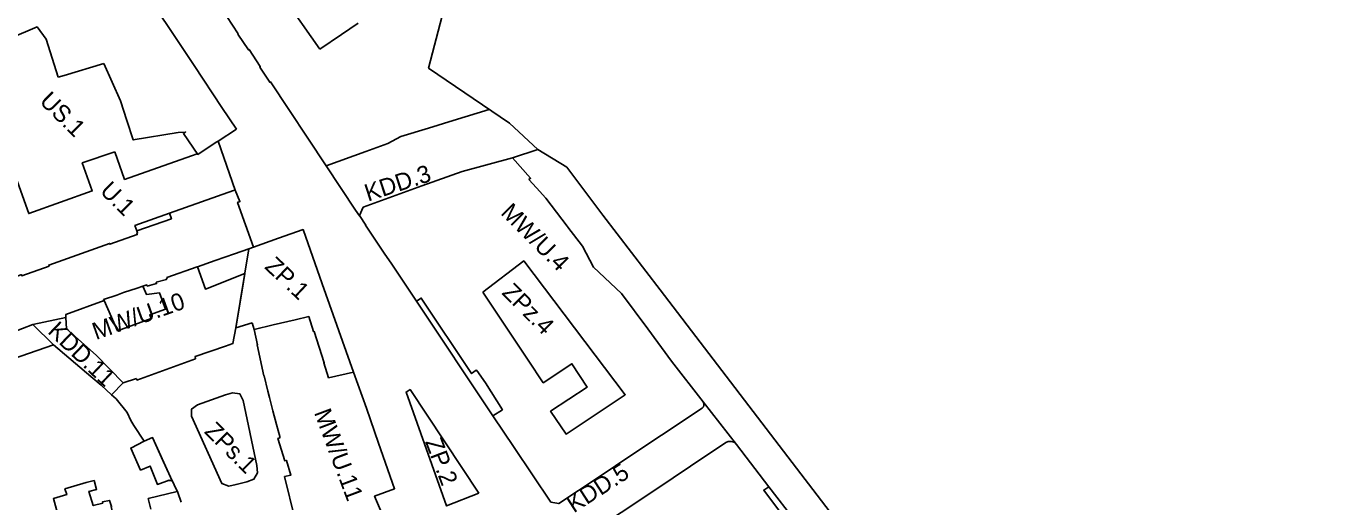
# Model space of a CAD drawing. Extents: x 7423835 to 7425280, y 5546086 to 5547600.
# Drawn here: x 7424593.5 to 7425051.2, y 5546812.9 to 5546978.5 of the extents above; entities that cross this region are included whole.
import ezdxf

# ---------------------------------------------------------------- set-up
doc = ezdxf.new("R2010")
doc.units = 0
for name, color, linetype in [('linie rozgraniczające', 7, 'Continuous'), ('nieprzekraczalne linie zabudowy', 7, 'Continuous'), ('obowiazujace linie zabudowy', 7, 'Continuous'), ('przeznaczenia terenów', 7, 'Continuous')]:
    doc.layers.add(name, color=color, linetype=linetype)

msp = doc.modelspace()

# ---------------------------------------------------------------- linework, layer by layer
at = {"layer": 'linie rozgraniczające'}
for p, q in [((7424600.36, 5546973.97), (7424604.55, 5546960.71)), ((7424626.3, 5546952.55), (7424620.51, 5546965.5)), ((7424643.29, 5546913.33), (7424665.59, 5546921.25)), ((7424665.59, 5546921.25), (7424665.59, 5546921.25)), ((7424707.32, 5546858.05), (7424696.51, 5546888.72)), ((7424595.78, 5546874.63), (7424607.27, 5546877.06)), ((7424672.07, 5546875.17), (7424666.41, 5546873.41)), ((7424627.31, 5546854.35), (7424623.19, 5546850.11)), ((7424698.63, 5546856.06), (7424707.32, 5546858.05)), ((7424829.01, 5546847.64), (7424840.65, 5546832.81)), ((7424637.43, 5546835.23), (7424643.66, 5546821.4))]:
    msp.add_line(p, q, dxfattribs=at)
for points in [[(7424666.6, 5546942.66), (7424661.55, 5546950.15), (7424651.91, 5546964.84), (7424642.84, 5546978.38), (7424633.62, 5546992.17)], [(7424680.83, 5546987.74), (7424682.81, 5546988.93), (7424695.69, 5546970.54)], [(7424697.84, 5546929.83), (7424678.43, 5546959.14), (7424678.21, 5546959), (7424674.71, 5546964.26), (7424674.92, 5546964.41), (7424671.02, 5546970.43), (7424670.81, 5546970.26), (7424667.13, 5546975.76), (7424667.19, 5546975.89), (7424663.24, 5546981.87)], [(7424738.23, 5546982.17), (7424733.48, 5546963.9), (7424761.63, 5546944.72), (7424771.54, 5546935.51), (7424781.55, 5546929.45), (7424782.68, 5546927.96)], [(7424600.37, 5546973.96), (7424597.25, 5546978.25), (7424587.81, 5546974.2), (7424588.98, 5546971.24), (7424582.7, 5546969.73), (7424580.63, 5546969.1), (7424581.87, 5546964.22), (7424583.37, 5546958.63), (7424584.27, 5546958.18), (7424585.02, 5546955.3)], [(7424695.69, 5546970.54), (7424703.23, 5546975.57), (7424709.02, 5546979.52)], [(7424620.51, 5546965.5), (7424606.66, 5546961.3), (7424604.55, 5546960.71)], [(7424626.3, 5546952.55), (7424628.5, 5546945.71), (7424630.69, 5546938.88), (7424646.35, 5546941.53)], [(7424697.84, 5546929.83), (7424711.67, 5546934.85), (7424719.32, 5546937.66), (7424723.88, 5546940.14), (7424733.46, 5546942.95), (7424742.05, 5546945.62)], [(7424742.05, 5546945.62), (7424754.59, 5546949.52)], [(7424666.6, 5546942.66), (7424660.28, 5546938.49), (7424659.62, 5546938.06), (7424653.17, 5546933.82), (7424648.19, 5546941.1), (7424648.93, 5546941.61), (7424646.35, 5546941.53), (7424645.56, 5546941.4)], [(7424660.28, 5546938.49), (7424666.17, 5546921.45), (7424665.59, 5546921.25)], [(7424580.32, 5546922.85), (7424589.85, 5546925.89), (7424594.37, 5546913.26), (7424616.46, 5546921.11), (7424612.99, 5546930.89), (7424624.28, 5546934.78)], [(7424652.99, 5546934.09), (7424651.04, 5546933.39), (7424627.71, 5546925.11), (7424624.28, 5546934.78)], [(7424771.54, 5546935.51), (7424762.74, 5546932.66), (7424745.17, 5546927.93), (7424731.08, 5546922.86), (7424731.08, 5546922.86)], [(7424829.01, 5546847.64), (7424818, 5546861.8), (7424809.76, 5546873.12), (7424800.59, 5546885.35), (7424790.9, 5546894.56), (7424787.04, 5546901.88), (7424781.98, 5546908.54), (7424781.84, 5546908.72), (7424781.7, 5546908.9), (7424774.31, 5546918.63), (7424771.03, 5546922.2), (7424768.4, 5546925.06), (7424768.97, 5546925.56), (7424762.74, 5546932.66)], [(7424709.45, 5546912.49), (7424708.1, 5546914.45), (7424697.84, 5546929.83)], [(7424782.68, 5546927.96), (7424794.17, 5546912.72), (7424814.07, 5546886.73), (7424849.43, 5546840.34), (7424880.72, 5546799.4), (7424914.19, 5546755.67), (7424955.9, 5546700.79), (7424956.48, 5546700.03), (7424989.28, 5546657.1), (7425017.11, 5546620.55), (7425027.02, 5546607.7), (7425026.41, 5546606.94), (7425028.62, 5546602.03), (7425031.34, 5546595.35), (7425032.03, 5546593.47), (7425044.64, 5546578.83), (7425047.45, 5546581.17), (7425051.22, 5546576.08)], [(7424731.08, 5546922.86), (7424710.75, 5546915.42), (7424709.41, 5546912.56)], [(7424666.17, 5546921.45), (7424667.85, 5546917.42), (7424667.05, 5546917.13), (7424672.57, 5546901.58)], [(7424547.9, 5546875.38), (7424554.86, 5546878.13), (7424554.8, 5546878.26), (7424564.11, 5546881.85), (7424577.56, 5546886.72), (7424591.55, 5546891.85), (7424591.81, 5546891.95), (7424591.94, 5546891.6), (7424601.42, 5546894.98), (7424601.32, 5546895.28), (7424622.5, 5546902.83), (7424622.61, 5546902.55), (7424632.09, 5546905.93), (7424631.95, 5546906.36), (7424632.21, 5546906.45), (7424631.94, 5546907.22), (7424644.01, 5546911.45), (7424643.29, 5546913.33), (7424643.29, 5546913.33)], [(7424829.01, 5546847.64), (7424829.26, 5546847.06), (7424829.32, 5546846.5), (7424829.13, 5546845.93), (7424828.67, 5546845.44), (7424814.48, 5546836.02), (7424804.24, 5546829.19), (7424792.87, 5546821.59), (7424778.79, 5546812.22), (7424776.08, 5546812.76), (7424763.28, 5546831.71), (7424755.89, 5546842.74), (7424729.31, 5546882.78), (7424720.47, 5546895.98), (7424718.31, 5546899.16), (7424718.21, 5546899.08), (7424711.48, 5546909.17), (7424711.6, 5546909.26), (7424709.41, 5546912.56)], [(7424653.13, 5546894.7), (7424659.24, 5546896.87), (7424665.91, 5546899.23), (7424670.96, 5546901.01), (7424672.57, 5546901.58), (7424681.29, 5546904.67)], [(7424696.51, 5546888.72), (7424689.83, 5546907.67), (7424681.29, 5546904.67)], [(7424689.83, 5546907.67), (7424689.83, 5546907.67)], [(7424666.41, 5546873.41), (7424670.96, 5546901.01)], [(7424631.81, 5546855.74), (7424627.25, 5546854.33), (7424617.8, 5546863.98), (7424607.48, 5546873.05), (7424607.27, 5546877.06), (7424607.21, 5546878.03), (7424620.54, 5546882.91), (7424620.38, 5546883.3), (7424625.01, 5546884.85), (7424627.32, 5546885.71), (7424632.06, 5546887.28), (7424634.07, 5546887.92), (7424635.46, 5546888.39), (7424635.57, 5546887.97), (7424638.83, 5546888.88), (7424638.73, 5546889.33), (7424642.29, 5546890.3), (7424642.23, 5546890.6), (7424642.52, 5546890.69), (7424642.44, 5546890.92), (7424652.96, 5546894.7), (7424652.99, 5546894.62), (7424653.13, 5546894.7)], [(7424698.63, 5546856.06), (7424697, 5546861.25), (7424697.2, 5546861.3), (7424693.64, 5546872.2), (7424693.44, 5546872.13), (7424691.76, 5546877.34), (7424687.06, 5546876.25), (7424679.46, 5546874.48), (7424672.74, 5546872.91)], [(7424602.91, 5546867.57), (7424595.78, 5546874.63), (7424545.36, 5546855.11)], [(7424666.41, 5546873.41), (7424665.37, 5546867.98), (7424662.78, 5546867.04)], [(7424686.98, 5546807.09), (7424683.36, 5546821.62), (7424685.58, 5546822.17), (7424684.02, 5546827.24), (7424683.45, 5546827.12), (7424681.07, 5546834.94), (7424681.78, 5546835.17), (7424681.67, 5546835.59), (7424680.54, 5546839.83), (7424679.33, 5546844.53), (7424678.12, 5546849.23), (7424677.57, 5546851.33), (7424676.32, 5546856.71), (7424676.2, 5546856.67), (7424673.78, 5546867.53), (7424673.95, 5546867.57), (7424672.74, 5546872.91), (7424672.07, 5546875.17)], [(7424545.36, 5546855.11), (7424546.87, 5546840.16), (7424553.83, 5546844.45), (7424560.78, 5546848.73), (7424561.2, 5546848.98), (7424561.48, 5546848.55), (7424564.87, 5546850.55), (7424564.41, 5546851.25), (7424578.02, 5546859.03), (7424582.88, 5546861.02), (7424583.08, 5546860.66), (7424602.91, 5546867.57)], [(7424602.91, 5546867.57), (7424615.93, 5546856.54), (7424619.5, 5546853.47), (7424623.19, 5546850.11), (7424624.72, 5546848.71), (7424628.59, 5546843.92), (7424629.86, 5546841.21), (7424630.88, 5546839.48), (7424634.49, 5546833.94), (7424637.43, 5546835.23)], [(7424662.78, 5546867.04), (7424652.21, 5546863.42), (7424652.37, 5546862.65), (7424632.02, 5546855.26), (7424631.81, 5546855.74)], [(7424707.32, 5546858.05), (7424711.92, 5546845.42), (7424716.09, 5546833.3), (7424721.67, 5546817.38), (7424714.67, 5546814.85), (7424719.05, 5546804.46), (7424719.1, 5546804.48), (7424723.96, 5546792.4), (7424723.75, 5546792.31), (7424723.82, 5546792.13), (7424725.89, 5546786.32), (7424726.44, 5546786.48), (7424730.93, 5546774.39), (7424730.57, 5546774.15), (7424730.99, 5546772.88), (7424730.86, 5546772.81), (7424730.99, 5546772.29), (7424732.04, 5546769.19), (7424733.94, 5546767.8), (7424736.9, 5546746.82), (7424739.64, 5546728.94), (7424739.1, 5546728.87)], [(7424665.28, 5546850.83), (7424662.79, 5546850.11), (7424653.13, 5546846.66), (7424651.04, 5546845.17), (7424650.94, 5546842.62), (7424661.55, 5546819.21), (7424663.98, 5546818.35), (7424666.48, 5546818.93), (7424670.28, 5546819.8), (7424672.7, 5546820.78), (7424673.99, 5546822.95), (7424673.75, 5546825.5), (7424669.02, 5546848.14), (7424667.82, 5546850.41), (7424665.28, 5546850.83)], [(7424751, 5546815.84), (7424727.03, 5546851.95), (7424725.66, 5546851.07), (7424739.75, 5546811.41), (7424751, 5546815.84)], [(7424786.09, 5546797.3), (7424786.62, 5546799.97), (7424800.5, 5546809.13), (7424812.54, 5546817.17), (7424824.68, 5546825.24), (7424836.91, 5546833.46), (7424837.76, 5546833.8), (7424838.78, 5546833.86), (7424839.7, 5546833.59), (7424839.91, 5546833.48), (7424840.65, 5546832.81), (7424851.85, 5546818.04), (7424861.02, 5546806.19), (7424869.71, 5546794.61), (7424878.29, 5546783.18), (7424885.98, 5546773.34), (7424894.86, 5546761.45), (7424905.23, 5546747.94)], [(7424643.66, 5546821.4), (7424646.21, 5546816.04), (7424647.41, 5546812.7)]]:
    msp.add_lwpolyline(points, dxfattribs=at)
msp.add_lwpolyline([(7424752.34, 5546885.83), (7424768.08, 5546862.21), (7424773.36, 5546854.3), (7424783.36, 5546860.95), (7424788.67, 5546852.82), (7424775.94, 5546844.41), (7424781.34, 5546836.44), (7424801.91, 5546850.16), (7424766.62, 5546896.78)], close=True, dxfattribs=at)
at = {"layer": 'nieprzekraczalne linie zabudowy'}
for points in [[(7424669.54, 5546892.41), (7424655.84, 5546886.92), (7424653.13, 5546894.7)], [(7424666.41, 5546873.41), (7424668.69, 5546887.21), (7424669.54, 5546892.41)], [(7424634.47, 5546833.92), (7424629.87, 5546831.57), (7424633.28, 5546823.9), (7424636.66, 5546825.3), (7424639.15, 5546818.88), (7424643.26, 5546820.39), (7424643.35, 5546820.16), (7424643.72, 5546820.31), (7424643.77, 5546820.2), (7424644.16, 5546820.35)]]:
    msp.add_lwpolyline(points, dxfattribs=at)
at = {"layer": 'obowiazujace linie zabudowy'}
msp.add_line((7424643.29, 5546913.33), (7424665.59, 5546921.25), dxfattribs=at)
for points in [[(7424666.6, 5546942.66), (7424661.55, 5546950.15), (7424651.91, 5546964.84), (7424642.84, 5546978.38), (7424633.62, 5546992.17)], [(7424663.24, 5546981.87), (7424667.19, 5546975.89), (7424667.13, 5546975.76), (7424670.81, 5546970.26), (7424671.02, 5546970.43), (7424674.92, 5546964.41), (7424674.71, 5546964.26), (7424678.21, 5546959), (7424678.43, 5546959.14), (7424697.84, 5546929.83)], [(7424697.84, 5546929.83), (7424711.67, 5546934.85), (7424719.32, 5546937.66), (7424723.88, 5546940.14), (7424733.46, 5546942.95), (7424742.05, 5546945.62)], [(7424742.05, 5546945.62), (7424754.59, 5546949.52)], [(7424660.28, 5546938.49), (7424666.6, 5546942.66)], [(7424665.59, 5546921.25), (7424666.17, 5546921.45), (7424660.28, 5546938.49)], [(7424762.74, 5546932.66), (7424745.17, 5546927.93), (7424731.08, 5546922.86)], [(7424829.01, 5546847.64), (7424818, 5546861.8), (7424809.76, 5546873.12), (7424800.59, 5546885.35), (7424790.9, 5546894.56), (7424787.04, 5546901.88), (7424781.98, 5546908.54), (7424781.84, 5546908.72), (7424781.7, 5546908.9), (7424774.31, 5546918.63), (7424771.03, 5546922.2), (7424768.4, 5546925.06), (7424768.97, 5546925.56), (7424762.74, 5546932.66)], [(7424731.08, 5546922.86), (7424710.75, 5546915.42), (7424709.41, 5546912.56)], [(7424631.94, 5546907.22), (7424631.29, 5546909.07), (7424643.29, 5546913.33)], [(7424643.29, 5546913.33), (7424643.29, 5546913.33)], [(7424709.41, 5546912.56), (7424711.6, 5546909.26), (7424711.48, 5546909.17), (7424718.21, 5546899.08), (7424718.31, 5546899.16), (7424720.47, 5546895.98), (7424729.31, 5546882.78), (7424730.95, 5546883.83), (7424748.44, 5546857.5), (7424750.06, 5546858.65), (7424750.25, 5546858.57), (7424753.24, 5546854.25), (7424759.18, 5546844.92), (7424755.89, 5546842.74), (7424763.28, 5546831.71), (7424776.08, 5546812.76)], [(7424547.9, 5546875.38), (7424554.86, 5546878.13), (7424554.8, 5546878.26), (7424564.11, 5546881.85), (7424577.56, 5546886.72), (7424591.55, 5546891.85), (7424591.81, 5546891.95), (7424591.94, 5546891.6), (7424601.42, 5546894.98), (7424601.32, 5546895.28), (7424622.5, 5546902.83), (7424622.61, 5546902.55), (7424632.09, 5546905.93), (7424631.95, 5546906.36), (7424632.21, 5546906.45), (7424631.94, 5546907.22)], [(7424653.13, 5546894.7), (7424652.99, 5546894.62), (7424652.96, 5546894.7), (7424642.44, 5546890.92), (7424642.52, 5546890.69), (7424642.23, 5546890.6), (7424642.29, 5546890.3), (7424638.73, 5546889.33), (7424638.83, 5546888.88), (7424635.57, 5546887.97), (7424635.46, 5546888.39), (7424634.07, 5546887.92)], [(7424634.21, 5546887.78), (7424635.27, 5546885.1), (7424639.89, 5546885.63), (7424641.89, 5546879.9), (7424636.47, 5546877.93), (7424636.94, 5546876.64), (7424625.21, 5546872.41), (7424620.54, 5546882.91)], [(7424620.54, 5546882.91), (7424607.21, 5546878.03), (7424607.27, 5546877.06), (7424607.48, 5546873.05), (7424617.8, 5546863.98), (7424627.25, 5546854.33), (7424631.81, 5546855.74)], [(7424602.91, 5546867.57), (7424595.78, 5546874.63), (7424545.36, 5546855.11)], [(7424631.81, 5546855.74), (7424632.02, 5546855.26), (7424652.37, 5546862.65), (7424652.21, 5546863.42), (7424662.78, 5546867.04), (7424665.37, 5546867.98), (7424666.41, 5546873.41)], [(7424672.74, 5546872.91), (7424673.95, 5546867.57), (7424673.78, 5546867.53), (7424676.2, 5546856.67), (7424676.32, 5546856.71), (7424677.57, 5546851.33), (7424678.12, 5546849.23), (7424679.33, 5546844.53), (7424680.54, 5546839.83), (7424681.67, 5546835.59), (7424681.78, 5546835.17), (7424681.07, 5546834.94), (7424683.45, 5546827.12), (7424684.02, 5546827.24), (7424685.58, 5546822.17), (7424683.36, 5546821.62), (7424686.98, 5546807.09)], [(7424739.1, 5546728.87), (7424739.64, 5546728.94), (7424736.9, 5546746.82), (7424733.94, 5546767.8), (7424732.04, 5546769.19), (7424730.99, 5546772.29), (7424730.86, 5546772.81), (7424730.99, 5546772.88), (7424730.57, 5546774.15), (7424730.93, 5546774.39), (7424726.44, 5546786.48), (7424725.89, 5546786.32), (7424723.82, 5546792.13), (7424723.75, 5546792.31), (7424723.96, 5546792.4), (7424719.1, 5546804.48), (7424719.05, 5546804.46), (7424714.67, 5546814.85), (7424721.67, 5546817.38), (7424716.09, 5546833.3), (7424711.92, 5546845.42), (7424707.32, 5546858.05)], [(7424778.79, 5546812.22), (7424792.87, 5546821.59), (7424804.24, 5546829.19), (7424814.48, 5546836.02), (7424828.67, 5546845.44), (7424829.13, 5546845.93), (7424829.32, 5546846.5), (7424829.26, 5546847.06), (7424829.01, 5546847.64)], [(7424644.16, 5546820.35), (7424643.66, 5546821.4), (7424640.54, 5546828.32), (7424637.43, 5546835.23), (7424634.47, 5546833.92)], [(7424905.23, 5546747.94), (7424894.86, 5546761.45), (7424892.94, 5546760.14), (7424884.03, 5546771.93), (7424865.53, 5546796.43), (7424854.53, 5546810.99), (7424850.14, 5546816.92), (7424851.85, 5546818.04), (7424840.65, 5546832.81), (7424839.91, 5546833.48), (7424839.7, 5546833.59), (7424838.78, 5546833.86), (7424837.76, 5546833.8), (7424836.91, 5546833.46), (7424824.68, 5546825.24), (7424812.54, 5546817.17), (7424800.5, 5546809.13), (7424786.62, 5546799.97), (7424786.09, 5546797.3)], [(7424617.07, 5546820.29), (7424614.34, 5546819.62), (7424606.95, 5546817.32), (7424607.56, 5546815.34), (7424602.92, 5546813.96), (7424606.74, 5546800), (7424611.02, 5546801.16), (7424611.48, 5546800.15), (7424613.91, 5546800.91)], [(7424624.67, 5546804.03), (7424624.69, 5546804.66), (7424623.01, 5546811.13), (7424623.17, 5546811.2), (7424622.42, 5546813.32), (7424619.96, 5546812.8), (7424620.09, 5546812.4), (7424616.79, 5546811.55), (7424615.3, 5546816.47), (7424617.95, 5546817.15), (7424617.07, 5546820.29)], [(7424646.04, 5546816.39), (7424635.93, 5546813.96), (7424636.8, 5546810.28)]]:
    msp.add_lwpolyline(points, dxfattribs=at)

# ---------------------------------------------------------------- texts
at = {"layer": 'przeznaczenia terenów'}
for s, rotation, p in [('US.1', 314.9764, (7424597.78, 5546952.04)), ('KDD.3', 18.0723, (7424712.39, 5546917.39)), ('U.1', 314.9764, (7424618.82, 5546920.76)), ('MW/U.4', 314.9764, (7424758.25, 5546913.2)), ('ZP.1', 316.7216, (7424676.11, 5546894.37)), ('MW/U.10', 19.5487, (7424617.74, 5546869.16)), ('ZPz.4', 314.9764, (7424758.69, 5546885.37)), ('KDD.11', 316.4431, (7424600.62, 5546871.86)), ('MW/U.11', 290.5593, (7424693.55, 5546843.94)), ('ZPs.1', 314.9764, (7424655.19, 5546837.05)), ('ZP.2', 290.8434, (7424732.2, 5546833.82)), ('KDD.5', 32.8514, (7424783.99, 5546808.8))]:
    msp.add_text(s, height=6, rotation=rotation, dxfattribs=at).set_placement(p)

doc.saveas('drawing.dxf')
